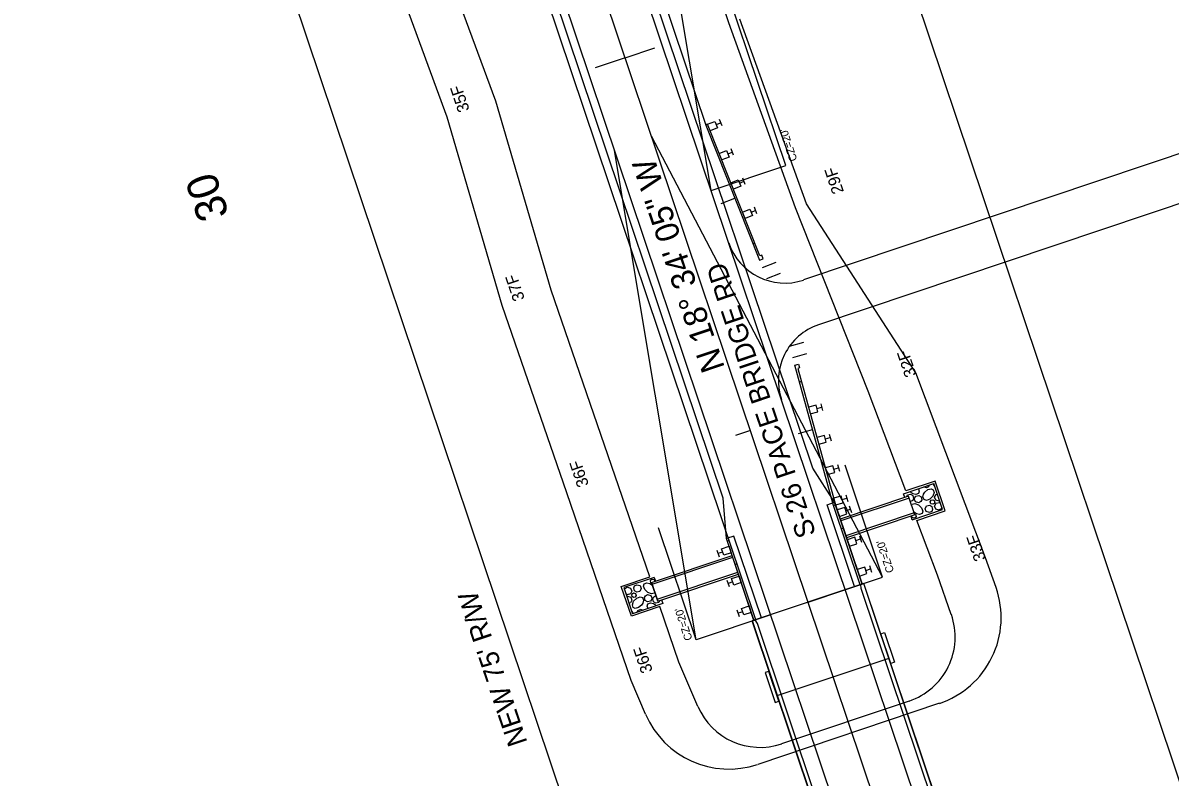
# Model space of a CAD drawing. Extents: x 1528853 to 1624411, y 1119753 to 1162242.
# Drawn here: x 1529554.1 to 1529845.6, y 1159919.3 to 1160111 of the extents above; entities that cross this region are included whole.
import ezdxf

# ---------------------------------------------------------------- set-up
doc = ezdxf.new("R2010")
doc.units = 0
for name, color, linetype in [('BR_CONCRETE', 7, 'Continuous'), ('Drainage-Trench', 7, 'Continuous'), ('RD_EX_Road Text', 7, 'Continuous'), ('RD_HC_Cl', 7, 'Continuous'), ('RD_HC_Data', 7, 'Continuous'), ('RD_HC_Data_Tic', 7, 'Continuous'), ('RD_HC_TX_Sta50', 7, 'Continuous'), ('RD_PD_BOC', 7, 'Continuous'), ('RD_PD_CstnLmt', 7, 'Continuous'), ('RD_PD_CstnLmt_TX', 7, 'Continuous'), ('RD_PD_DR_ErosCtrl', 7, 'Continuous'), ('RD_PD_DR_Inlet', 7, 'Continuous'), ('RD_PD_Driveway', 7, 'Continuous'), ('RD_PD_Final_TrvlWay', 7, 'Continuous'), ('RD_PD_GR', 7, 'Continuous'), ('RD_PD_PaveDit', 7, 'Continuous'), ('RD_PD_PaveShd', 7, 'Continuous'), ('RD_PD_RW', 7, 'Continuous'), ('RD_Sketch8', 7, 'Continuous')]:
    doc.layers.add(name, color=color, linetype=linetype)

# ---------------------------------------------------------------- blocks, each defined once
blk = doc.blocks.new('Guardrail_MTBBC2_Transition')
at = {"layer": 'RD_PD_GR'}
for p, q in [((3.875, 3.75), (2.125, 3.75)), ((3, 2.5), (3, 3.75)), ((11.875, 3.75), (10.125, 3.75)), ((11, 2.5), (11, 3.75)), ((19.875, 3.75), (18.125, 3.75)), ((19, 2.5), (19, 3.75)), ((0, 0.5), (0, 0)), ((21.25, 0.5), (0, 0.5)), ((0, 0), (21.25, 0)), ((2.125, 0.5), (2.125, 2.5)), ((2.125, 2.5), (3.875, 2.5)), ((3.875, 0.5), (2.125, 0.5)), ((3.875, 2.5), (3.875, 0.5)), ((10.125, 0.5), (10.125, 2.5)), ((10.125, 2.5), (11.875, 2.5)), ((11.875, 0.5), (10.125, 0.5)), ((11.875, 2.5), (11.875, 0.5)), ((15, 0.5), (15, 0)), ((18.125, 0.5), (18.125, 2.5)), ((18.125, 2.5), (19.875, 2.5)), ((19.875, 0.5), (18.125, 0.5)), ((19.875, 2.5), (19.875, 0.5)), ((21.25, 0), (21.25, 0.5))]:
    blk.add_line(p, q, dxfattribs=at)
blk = doc.blocks.new('Guardrail_MT2_Leading_with_Buffer')
at = {"layer": 'RD_PD_GR'}
for p, q in [((38.94, 2.11), (38.74, 5.85)), ((41.94, 2.27), (41.74, 6.01)), ((1.55, 3.84), (-0.2, 3.74)), ((0.74, 2.54), (0.67, 3.79)), ((9.53, 4.27), (7.79, 4.18)), ((7.85, 2.93), (9.6, 3.02)), ((7.96, 0.93), (7.85, 2.93)), ((8.73, 2.98), (8.66, 4.22)), ((9.6, 3.02), (9.71, 1.03)), ((17.52, 4.7), (15.77, 4.61)), ((15.84, 3.36), (17.59, 3.45)), ((15.95, 1.36), (15.84, 3.36)), ((16.72, 3.41), (16.65, 4.66)), ((17.59, 3.45), (17.7, 1.46)), ((25.51, 5.13), (23.76, 5.04)), ((23.83, 3.79), (25.58, 3.89)), ((23.94, 1.79), (23.83, 3.79)), ((24.7, 3.84), (24.64, 5.09)), ((25.58, 3.89), (25.69, 1.89)), ((36.89, 3), (35.89, 2.94)), ((35.89, 2.94), (35.92, 2.44)), ((36.95, 2), (36.89, 3)), ((-0.13, 2.5), (1.61, 2.59)), ((-0.03, 0.5), (-0.13, 2.5)), ((35.92, 2.44), (-0.03, 0.5)), ((1.72, 0.59), (-0.03, 0.5)), ((-0.03, 0.5), (0, 0)), ((0, 0), (36.95, 2)), ((1.61, 2.59), (1.72, 0.59)), ((9.71, 1.03), (7.96, 0.93)), ((17.7, 1.46), (15.95, 1.36)), ((20.17, -2.67), (19.97, 1.08)), ((25.69, 1.89), (23.94, 1.79)), ((32.43, 2.25), (32.45, 1.75))]:
    blk.add_line(p, q, dxfattribs=at)

msp = doc.modelspace()

# ---------------------------------------------------------------- linework, layer by layer
at = {"layer": 'BR_CONCRETE'}
for p, q in [((1529767.81, 1159968.55), (1529739.37, 1159959)), ((1529767.1, 1159967.26), (1529767.02, 1159968.29)), ((1529801.49, 1159864.88), (1529767.1, 1159967.26)), ((1529802.75, 1159864.25), (1529767.73, 1159968.53)), ((1529802.83, 1159864.28), (1529767.81, 1159968.55)), ((1529774.39, 1159854.72), (1529739.37, 1159959)), ((1529774.47, 1159854.75), (1529739.45, 1159959.03)), ((1529740.71, 1159958.4), (1529740.16, 1159959.26)), ((1529775.1, 1159856.02), (1529740.71, 1159958.4)), ((1529745.74, 1159940.04), (1529774.17, 1159949.59))]:
    msp.add_line(p, q, dxfattribs=at)
for points in [[(1529775.6, 1159948.49), (1529774.65, 1159948.17), (1529772.1, 1159955.75), (1529773.05, 1159956.07)], [(1529745.27, 1159938.3), (1529746.21, 1159938.62), (1529743.67, 1159946.2), (1529742.72, 1159945.88)]]:
    msp.add_lwpolyline(points, close=True, dxfattribs=at)
at = {"layer": 'Drainage-Trench'}
for p, q in [((1529777.85, 1159991.35), (1529785.55, 1159993.94)), ((1529787.77, 1159987.3), (1529785.55, 1159993.94)), ((1529778.17, 1159990.41), (1529777.85, 1159991.35)), ((1529780.71, 1159985.98), (1529779.12, 1159990.72)), ((1529780.08, 1159984.72), (1529779.76, 1159985.67)), ((1529780.08, 1159984.72), (1529787.77, 1159987.3)), ((1529714.48, 1159970.07), (1529706.79, 1159967.48)), ((1529706.79, 1159967.48), (1529709.02, 1159960.85)), ((1529713.85, 1159968.8), (1529715.45, 1159964.06)), ((1529714.48, 1159970.07), (1529714.8, 1159969.12)), ((1529716.4, 1159964.38), (1529716.71, 1159963.43)), ((1529716.71, 1159963.43), (1529709.02, 1159960.85))]:
    msp.add_line(p, q, dxfattribs=at)
at = {"layer": 'RD_HC_Cl'}
msp.add_line((1529913.5, 1159487.74), (1529500.12, 1160718.34), dxfattribs=at)
at = {"layer": 'RD_HC_Data_Tic'}
for p, q in [((1529707.1, 1160102.18), (1529714.68, 1160104.72)), ((1529707.1, 1160102.18), (1529699.51, 1160099.63)), ((1529738.94, 1160007.38), (1529735.15, 1160006.11))]:
    msp.add_line(p, q, dxfattribs=at)
at = {"layer": 'RD_PD_BOC'}
for p, q in [((1529758.46, 1159988.53), (1529760.35, 1159989.17)), ((1529765.44, 1159967.76), (1529758.46, 1159988.53)), ((1529767.33, 1159968.39), (1529760.35, 1159989.17)), ((1529734.76, 1159980.57), (1529732.86, 1159979.93)), ((1529739.84, 1159959.16), (1529732.86, 1159979.93)), ((1529741.74, 1159959.79), (1529734.76, 1159980.57))]:
    msp.add_line(p, q, dxfattribs=at)
at = {"layer": 'RD_PD_CstnLmt'}
for p, q in [((1529733.43, 1160111.02), (1529718.39, 1160158.72)), ((1529674.28, 1160091.15), (1529656.96, 1160138.08)), ((1529750.42, 1160063.98), (1529733.43, 1160111.02)), ((1529688.29, 1160043.11), (1529674.28, 1160091.15)), ((1529768.87, 1160017.43), (1529750.42, 1160063.98)), ((1529704.58, 1159995.84), (1529688.29, 1160043.11)), ((1529778.42, 1159992.07), (1529768.87, 1160017.43)), ((1529713.37, 1159970.22), (1529704.58, 1159995.84)), ((1529785.86, 1159994.57), (1529778.42, 1159992.07)), ((1529788.41, 1159986.99), (1529785.86, 1159994.57)), ((1529781.24, 1159984.58), (1529788.41, 1159986.99)), ((1529786.49, 1159970.61), (1529781.24, 1159984.58)), ((1529706.15, 1159967.8), (1529713.37, 1159970.22)), ((1529790, 1159960.63), (1529786.49, 1159970.61)), ((1529708.7, 1159960.21), (1529706.15, 1159967.8)), ((1529715.96, 1159962.65), (1529708.7, 1159960.21)), ((1529720.8, 1159948.54), (1529715.96, 1159962.65)), ((1529725.61, 1159937.3), (1529720.8, 1159948.54)), ((1529779.26, 1159938.64), (1529746.89, 1159927.76))]:
    msp.add_line(p, q, dxfattribs=at)
for centre, start, end in [((1529773.79, 1159954.93), 288.568, 19.3726), ((1529741.42, 1159944.06), 203.162, 288.568)]:
    msp.add_arc(centre, 17.19, start, end, dxfattribs=at)
at = {"layer": 'RD_PD_DR_ErosCtrl'}
for p, q in [((1529661.93, 1160087.08), (1529644.75, 1160133.61)), ((1529753.24, 1160065), (1529736.28, 1160111.98)), ((1529675.9, 1160039.17), (1529661.93, 1160087.08)), ((1529781, 1160022.12), (1529753.24, 1160065)), ((1529692.29, 1159991.61), (1529675.9, 1160039.17)), ((1529798.71, 1159975.06), (1529781, 1160022.12)), ((1529708.66, 1159943.87), (1529692.29, 1159991.61)), ((1529801.37, 1159967.5), (1529798.71, 1159975.06)), ((1529712.33, 1159935.31), (1529708.66, 1159943.87)), ((1529786.99, 1159938.07), (1529740.8, 1159922.55))]:
    msp.add_line(p, q, dxfattribs=at)
for centre, start, end in [((1529779.67, 1159959.87), 288.568, 19.3726), ((1529733.47, 1159944.36), 203.162, 288.568)]:
    msp.add_arc(centre, 23, start, end, dxfattribs=at)
at = {"layer": 'RD_PD_DR_Inlet'}
for p, q in [((1529779.12, 1159990.72), (1529761.79, 1159984.9)), ((1529780.71, 1159985.98), (1529779.12, 1159990.72)), ((1529779.27, 1159990.25), (1529761.95, 1159984.43)), ((1529780.55, 1159986.46), (1529763.22, 1159980.64)), ((1529780.71, 1159985.98), (1529763.38, 1159980.16)), ((1529713.85, 1159968.8), (1529734.3, 1159975.67)), ((1529714.01, 1159968.33), (1529734.45, 1159975.19)), ((1529715.29, 1159964.53), (1529735.73, 1159971.4)), ((1529715.45, 1159964.06), (1529735.89, 1159970.93)), ((1529715.45, 1159964.06), (1529713.85, 1159968.8))]:
    msp.add_line(p, q, dxfattribs=at)
at = {"layer": 'RD_PD_Driveway'}
for p, q in [((1529894.94, 1160093.54), (1529752.45, 1160045.68)), ((1529898.76, 1160082.17), (1529756.27, 1160034.3))]:
    msp.add_line(p, q, dxfattribs=at)
for centre, start, end in [((1529747.67, 1160059.89), 198.568, 288.568), ((1529761.05, 1160020.08), 108.568, 198.568)]:
    msp.add_arc(centre, 15, start, end, dxfattribs=at)
at = {"layer": 'RD_PD_Final_TrvlWay'}
for p, q in [((1529922.97, 1159490.92), (1529689.19, 1160186.88)), ((1529904.02, 1159484.55), (1529670.23, 1160180.51))]:
    msp.add_line(p, q, dxfattribs=at)
at = {"layer": 'RD_PD_GR'}
for p, q in [((1529699.75, 1160168.01), (1529727.61, 1160085.07)), ((1529734.82, 1159975.67), (1529673.21, 1160159.1))]:
    msp.add_line(p, q, dxfattribs=at)
at = {"layer": 'RD_PD_PaveDit'}
for p, q in [((1529779.77, 1159991.64), (1529779.53, 1159991.92)), ((1529783.66, 1159992.82), (1529782.89, 1159993.05)), ((1529779.64, 1159989.34), (1529779.57, 1159989.36)), ((1529780.68, 1159986.54), (1529780.42, 1159986.85)), ((1529713.89, 1159968.25), (1529714.14, 1159967.94)), ((1529714.92, 1159965.44), (1529714.99, 1159965.42)), ((1529710.9, 1159961.97), (1529711.67, 1159961.74)), ((1529714.79, 1159963.14), (1529715.03, 1159962.87))]:
    msp.add_line(p, q, dxfattribs=at)
for points in [[(1529784.41, 1159993.56), (1529784.21, 1159993.13), (1529783.66, 1159992.82)], [(1529785.74, 1159993.37), (1529785.53, 1159993.61), (1529785.46, 1159993.91)], [(1529778.61, 1159990.55), (1529778.87, 1159991.06), (1529779.67, 1159991.24), (1529780.22, 1159990.9), (1529780.42, 1159990.13), (1529780.19, 1159989.66), (1529779.64, 1159989.34)], [(1529781.63, 1159992.62), (1529781.85, 1159992.03), (1529781.66, 1159991.43), (1529780.99, 1159991.15), (1529780.24, 1159991.34), (1529779.73, 1159991.67)], [(1529781.74, 1159989.05), (1529780.9, 1159989.3), (1529780.6, 1159990.04), (1529780.97, 1159990.76), (1529781.77, 1159990.94), (1529782.32, 1159990.6), (1529782.52, 1159989.83), (1529782.29, 1159989.36), (1529781.74, 1159989.05)], [(1529783.27, 1159991.73), (1529784.04, 1159992.39), (1529784.89, 1159992.59), (1529785.41, 1159992.35), (1529785.62, 1159991.68), (1529785.28, 1159990.73), (1529784.52, 1159989.96), (1529783.66, 1159989.66), (1529783.06, 1159989.84), (1529782.78, 1159990.51), (1529782.97, 1159991.26), (1529783.3, 1159991.77)], [(1529786.88, 1159989.46), (1529786.04, 1159989.71), (1529785.74, 1159990.46), (1529786.11, 1159991.17), (1529786.45, 1159991.25)], [(1529779.91, 1159988.36), (1529780.06, 1159988.68), (1529780.73, 1159988.89), (1529781.68, 1159988.55), (1529782.45, 1159987.79), (1529782.75, 1159986.93), (1529782.57, 1159986.33), (1529781.9, 1159986.05), (1529781.15, 1159986.24), (1529780.64, 1159986.57)], [(1529784.48, 1159986.56), (1529783.63, 1159986.8), (1529783.33, 1159987.55), (1529783.71, 1159988.27), (1529784.5, 1159988.45), (1529785.05, 1159988.11), (1529785.25, 1159987.34), (1529785.03, 1159986.87), (1529784.48, 1159986.56)], [(1529785.32, 1159988.67), (1529784.81, 1159988.82), (1529784.63, 1159989.26), (1529784.86, 1159989.69), (1529785.33, 1159989.8), (1529785.66, 1159989.6), (1529785.78, 1159989.14), (1529785.65, 1159988.85), (1529785.32, 1159988.67)], [(1529786.88, 1159987.21), (1529786.04, 1159987.46), (1529785.74, 1159988.21), (1529786.11, 1159988.93), (1529786.91, 1159989.11), (1529787.23, 1159988.91)], [(1529787.02, 1159989.54), (1529786.88, 1159989.46)], [(1529787.59, 1159987.85), (1529787.43, 1159987.53), (1529786.88, 1159987.22)], [(1529780.57, 1159985.13), (1529780.07, 1159985.28), (1529779.89, 1159985.71)], [(1529780.62, 1159986.24), (1529780.92, 1159986.06), (1529781.04, 1159985.6), (1529780.9, 1159985.31), (1529780.57, 1159985.13)], [(1529706.97, 1159966.93), (1529707.13, 1159967.26), (1529707.68, 1159967.57)], [(1529707.68, 1159967.57), (1529708.52, 1159967.32), (1529708.82, 1159966.57), (1529708.45, 1159965.86), (1529707.65, 1159965.67), (1529707.33, 1159965.88)], [(1529710.09, 1159968.23), (1529710.93, 1159967.98), (1529711.23, 1159967.23), (1529710.86, 1159966.52), (1529710.06, 1159966.33), (1529709.51, 1159966.67), (1529709.31, 1159967.45), (1529709.54, 1159967.92), (1529710.09, 1159968.23)], [(1529714.65, 1159966.43), (1529714.51, 1159966.11), (1529713.83, 1159965.9), (1529712.88, 1159966.24), (1529712.11, 1159967), (1529711.81, 1159967.86), (1529711.99, 1159968.46), (1529712.66, 1159968.73), (1529713.41, 1159968.55), (1529713.92, 1159968.22)], [(1529713.94, 1159968.54), (1529713.65, 1159968.73), (1529713.53, 1159969.19), (1529713.66, 1159969.47), (1529713.99, 1159969.66)], [(1529713.99, 1159969.66), (1529714.5, 1159969.51), (1529714.67, 1159969.07)], [(1529707.54, 1159965.24), (1529707.68, 1159965.32)], [(1529707.68, 1159965.32), (1529708.53, 1159965.07), (1529708.83, 1159964.33), (1529708.45, 1159963.61), (1529708.11, 1159963.53)], [(1529709.25, 1159966.12), (1529709.75, 1159965.97), (1529709.93, 1159965.52), (1529709.71, 1159965.09), (1529709.23, 1159964.98), (1529708.9, 1159965.19), (1529708.78, 1159965.65), (1529708.91, 1159965.93), (1529709.25, 1159966.12)], [(1529711.29, 1159963.05), (1529710.52, 1159962.4), (1529709.67, 1159962.19), (1529709.16, 1159962.43), (1529708.95, 1159963.1), (1529709.28, 1159964.06), (1529710.05, 1159964.82), (1529710.9, 1159965.13), (1529711.51, 1159964.95), (1529711.78, 1159964.27), (1529711.59, 1159963.53), (1529711.26, 1159963.02)], [(1529712.82, 1159965.74), (1529713.66, 1159965.49), (1529713.96, 1159964.74), (1529713.59, 1159964.02), (1529712.79, 1159963.84), (1529712.24, 1159964.18), (1529712.05, 1159964.95), (1529712.27, 1159965.42), (1529712.82, 1159965.74)], [(1529715.95, 1159964.23), (1529715.69, 1159963.73), (1529714.9, 1159963.55), (1529714.35, 1159963.89), (1529714.15, 1159964.66), (1529714.37, 1159965.13), (1529714.92, 1159965.44)], [(1529708.82, 1159961.42), (1529709.03, 1159961.18), (1529709.1, 1159960.87)], [(1529710.15, 1159961.23), (1529710.35, 1159961.65), (1529710.9, 1159961.96)], [(1529712.93, 1159962.16), (1529712.72, 1159962.76), (1529712.9, 1159963.36), (1529713.57, 1159963.63), (1529714.32, 1159963.45), (1529714.83, 1159963.12)]]:
    msp.add_lwpolyline(points, dxfattribs=at)
at = {"layer": 'RD_PD_PaveShd'}
for p, q in [((1529754.8, 1159997.85), (1529701.25, 1160157.28)), ((1529732.05, 1159990.21), (1529678.5, 1160149.61)), ((1529760.35, 1159989.17), (1529754.8, 1159997.85)), ((1529732.86, 1159979.93), (1529732.05, 1159990.21))]:
    msp.add_line(p, q, dxfattribs=at)
at = {"layer": 'RD_PD_RW'}
for p, q in [((1529881.68, 1159817.98), (1529571.21, 1160742.22)), ((1529715.61, 1159841.31), (1529429.02, 1160694.46))]:
    msp.add_line(p, q, dxfattribs=at)
at = {"layer": 'RD_Sketch8'}
for p, q in [((1529747.95, 1160074.76), (1529708.15, 1160193.25)), ((1529728.99, 1160068.39), (1529708.15, 1160193.25)), ((1529772.55, 1159970.14), (1529713.78, 1160082.27)), ((1529725.15, 1159954.22), (1529704.3, 1160079.08)), ((1529728.99, 1160068.39), (1529747.95, 1160074.76)), ((1529772.55, 1159970.14), (1529762.99, 1159998.58)), ((1529772.55, 1159970.14), (1529762.99, 1159998.58)), ((1529725.15, 1159954.22), (1529715.6, 1159982.66)), ((1529753.59, 1159963.78), (1529772.55, 1159970.14)), ((1529753.59, 1159963.78), (1529772.55, 1159970.14)), ((1529744.11, 1159960.59), (1529725.15, 1159954.22))]:
    msp.add_line(p, q, dxfattribs=at)

# ---------------------------------------------------------------- block references
at = {"layer": 'RD_PD_BOC', "yscale": -0.9999999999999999, "rotation": 108.56800570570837}
msp.add_blockref('Guardrail_MTBBC2_Transition', (1529766.86, 1159968.23), dxfattribs=at)
at = {"layer": 'RD_PD_BOC', "rotation": 108.5680057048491}
msp.add_blockref('Guardrail_MTBBC2_Transition', (1529740.32, 1159959.32), dxfattribs=at)
at = {"layer": 'RD_PD_GR', "rotation": -71.43199429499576}
msp.add_blockref('Guardrail_MT2_Leading_with_Buffer', (1529727.61, 1160085.07), dxfattribs=at)
at = {"layer": 'RD_PD_GR', "yscale": -1, "rotation": 108.56800570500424}
msp.add_blockref('Guardrail_MT2_Leading_with_Buffer', (1529760.09, 1159988.38), dxfattribs=at)

# ---------------------------------------------------------------- texts
at = {"layer": 'RD_EX_Road Text'}
msp.add_text('S-26 PACE BRIDGE RD', height=5, rotation=108.5527, dxfattribs=at).set_placement((1529755.67, 1159981.14))
at = {"layer": 'RD_HC_Data'}
msp.add_text('N 18%%d 34\' 05" W', height=6, rotation=108.568, dxfattribs=at).set_placement((1529732.51, 1160023.42))
at = {"layer": 'RD_HC_TX_Sta50'}
msp.add_text('30', height=8, rotation=108.568, dxfattribs=at).set_placement((1529606.56, 1160062.29))
at = {"layer": 'RD_PD_CstnLmt_TX'}
for s, p in [('35F', (1529667.64, 1160088.92)), ('29F', (1529762.74, 1160068.12)), ('37F', (1529681.65, 1160040.88)), ('32F', (1529781.19, 1160021.57)), ('36F', (1529697.95, 1159993.61)), ('33F', (1529798.82, 1159974.75)), ('36F', (1529714.17, 1159946.31))]:
    msp.add_text(s, height=3, rotation=108.568, dxfattribs=at).set_placement(p)
at = {"layer": 'RD_PD_RW'}
msp.add_text("NEW 75' R/W", height=5, rotation=108.5527, dxfattribs=at).set_placement((1529682.33, 1159928.16))
at = {"layer": 'RD_Sketch8'}
for p in [(1529750.9, 1160076.22), (1529775.49, 1159971.6), (1529775.49, 1159971.6), (1529724.26, 1159954.39)]:
    msp.add_text("CZ=20'", height=2, rotation=108.3453, dxfattribs=at).set_placement(p)

doc.saveas('drawing.dxf')
